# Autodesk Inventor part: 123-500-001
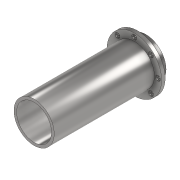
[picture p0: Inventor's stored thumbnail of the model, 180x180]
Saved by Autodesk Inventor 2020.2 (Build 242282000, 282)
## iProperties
Manager: www.cadconsulting.pl
Company: Fabian Stasiak CAD Consulting
Created: 2019-11
Part Number: 123-500-001
Material: Stal, odlew
Document SubType Name: Modeling
Designer: F.Stasiak
Density: 7.85 g/cm^3
Appearance: Częściowo polerowany
Description: Prowadnica
Mass: 427535 g
Surface Area: 36920 cm^2
Volume: 54463.1 cm^3
Author: F.Stasiak
Subject: Zbiór ćwiczeń. Autodesk Inventor 2020. Kurs podstawowy
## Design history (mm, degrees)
sketch "Szkic1"
  geometry: C1 r 225 at (0, 0); C2 r 195 at (0, 0); 1 further point
  constraints: 2 centre point, 2 coincident
  dimensions: "d0" = 450 diameter of C1; "d1" = 30 radial gap between concentric circles of C1 C2
extrude "Wyciągnięcie proste1" new body sketch "Szkic1" distance "d2" = 1250; taper "d3" = 0 deg
sketch "Szkic2"
  geometry: L1 (225, 0)-(225, 1250) reference; L2 (225, 90)-(305, 90); L3 (305, 90)-(305, 130); L4 (305, 130)-(225, 130); L5 (225, 130)-(225, 90); L6 (0, -250)-(0, 1500) reference; 2 further points
  constraints: 8 end point, 2 parallel, 1 horizontal, 1 perpendicular, 1 point on line
  dimensions: "d4" = 80 distance of L4.end L3.end; "d5" = 40 distance of L3.end L2.end; "d6" = 90 distance of L2.start L1.start
revolve "Obrót1" sketch "Szkic2" stored, may be unused: angle "d7" = 90 deg
sketch "Szkic3"
  geometry: 2 further points
  constraints: 1 vertical alignment
  dimensions: "d8" = 265 distance of point (0, 0) point (0, 265)
hole "Otwór1" sketch "Szkic3" at (0, 265) diameter "d9" = 22; stored, may be unused: countersink angle "d13" = 90 deg, drill point angle "d15" = 118 deg; dims "d10" = 6, "d11" = 55, "d12" = 14, "d14" = 8
pattern_circular "Szyk kołowy1" dims angle "d17" = 360 deg
node "Bryła1"
